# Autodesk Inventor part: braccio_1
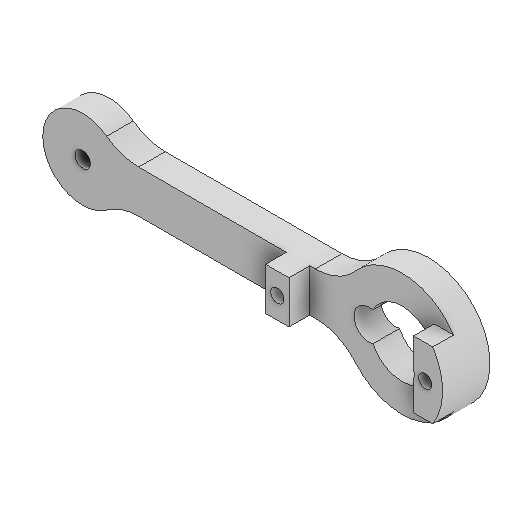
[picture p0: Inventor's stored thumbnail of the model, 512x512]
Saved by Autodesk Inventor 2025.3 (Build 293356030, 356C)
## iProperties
Created: 2026-03
Part Number: braccio_1
Material: Generico
Document SubType Name: Modeling
Designer: Ryzen5700u
Density: 1 g/cm^3
Appearance: Default
Author: Ryzen5700u
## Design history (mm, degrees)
sketch "Schizzo1"
  geometry: L1 (-60, 4)-(0, 4); L2 (0, 4)-(0, -4); L3 (0, -4)-(-60, -4); L4 (-60, -4)-(-60, 4); L5 (0, 0)-(13.023, 0); C1 r 11.5 at (0, 0); C2 r 7.5 at (-60, 0); 5 further points
  constraints: 10 end point, 2 centre point, 2 horizontal, 2 midpoint, 2 parallel, 1 coincident, 1 perpendicular, 1 other
  dimensions: "d0" = 23 diameter of C1; "d3" = 60 distance of L1.start L1.end; "d4" = 15 diameter of C2; "d16" = 8 distance between parallel lines of L1 L3
extrude "Estrusione1" new body sketch "Schizzo1" distance "d1" = 5; taper "d2" = 0 deg
fillet "Raccordo1" dims "d5" = 10
sketch "Schizzo2"
  geometry: L1 (-0.548, -2.337)-(-0.45, -2.358) reference; L2 (-0.569, -2.434)-(-0.548, -2.337) reference; L3 (-0.694, -2.298)-(-0.725, -2.393) reference; L4 (-0.789, -2.267)-(-0.694, -2.298) reference; L5 (-0.82, -2.362)-(-0.789, -2.267) reference; L6 (-0.93, -2.213)-(-0.971, -2.304) reference; L7 (-1.022, -2.172)-(-0.93, -2.213) reference; L8 (-1.062, -2.263)-(-1.022, -2.172) reference; L9 (-1.157, -2.103)-(-1.206, -2.19) reference; L10 (-1.243, -2.053)-(-1.157, -2.103) reference; L11 (-1.293, -2.14)-(-1.243, -2.053) reference; L12 (-1.37, -1.971)-(-1.429, -2.052) reference; L13 (-1.451, -1.912)-(-1.37, -1.971) reference; L14 (-1.51, -1.993)-(-1.451, -1.912) reference; L15 (-1.569, -1.817)-(-1.635, -1.891) reference; L16 (-1.643, -1.75)-(-1.569, -1.817) reference; L17 (-1.71, -1.824)-(-1.643, -1.75) reference; L18 (-1.75, -1.643)-(-1.824, -1.71) reference; L19 (-1.817, -1.569)-(-1.75, -1.643) reference; L20 (-1.891, -1.635)-(-1.817, -1.569) reference; L21 (-1.912, -1.451)-(-1.993, -1.51) reference; L22 (-1.971, -1.37)-(-1.912, -1.451) reference; L23 (-2.052, -1.429)-(-1.971, -1.37) reference; L24 (-2.053, -1.243)-(-2.14, -1.293) reference; L25 (-2.103, -1.157)-(-2.053, -1.243) reference; L26 (-2.19, -1.206)-(-2.103, -1.157) reference; L27 (-2.172, -1.022)-(-2.263, -1.062) reference; L28 (-2.213, -0.93)-(-2.172, -1.022) reference; L29 (-2.304, -0.971)-(-2.213, -0.93) reference; L30 (-2.267, -0.789)-(-2.362, -0.82) reference; L31 (-2.298, -0.694)-(-2.267, -0.789) reference; L32 (-2.393, -0.725)-(-2.298, -0.694) reference; L33 (-2.337, -0.548)-(-2.434, -0.569) reference; L34 (-2.358, -0.45)-(-2.337, -0.548) reference; L35 (-2.455, -0.471)-(-2.358, -0.45) reference; L36 (-2.382, -0.301)-(-2.481, -0.311) reference; L37 (-2.392, -0.201)-(-2.382, -0.301) reference; L38 (-2.491, -0.212)-(-2.392, -0.201) reference; L39 (-2.4, -0.05)-(-2.499, -0.05) reference; L40 (-2.4, 0.05)-(-2.4, -0.05) reference; L41 (-2.499, 0.05)-(-2.4, 0.05) reference; L42 (-2.392, 0.201)-(-2.491, 0.212) reference; L43 (-2.382, 0.301)-(-2.392, 0.201) reference; L44 (-2.481, 0.311)-(-2.382, 0.301) reference; L45 (-2.358, 0.45)-(-2.455, 0.471) reference; L46 (-2.337, 0.548)-(-2.358, 0.45) reference; L47 (-2.434, 0.569)-(-2.337, 0.548) reference; L48 (-2.298, 0.694)-(-2.393, 0.725) reference; L49 (-2.267, 0.789)-(-2.298, 0.694) reference; L50 (-2.362, 0.82)-(-2.267, 0.789) reference; L51 (-2.213, 0.93)-(-2.304, 0.971) reference; L52 (-2.172, 1.022)-(-2.213, 0.93) reference; L53 (-2.263, 1.062)-(-2.172, 1.022) reference; L54 (-2.103, 1.157)-(-2.19, 1.206) reference; L55 (-2.053, 1.243)-(-2.103, 1.157) reference; L56 (-2.14, 1.293)-(-2.053, 1.243) reference; L57 (-1.971, 1.37)-(-2.052, 1.429) reference; L58 (-1.912, 1.451)-(-1.971, 1.37) reference; L59 (-1.993, 1.51)-(-1.912, 1.451) reference; L60 (-1.817, 1.569)-(-1.891, 1.635) reference; L61 (-1.75, 1.643)-(-1.817, 1.569) reference; L62 (-1.824, 1.71)-(-1.75, 1.643) reference; L63 (-1.643, 1.75)-(-1.71, 1.824) reference; L64 (-1.569, 1.817)-(-1.643, 1.75) reference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; A1 r 6 centre (0, 0) between (-5.416, -2.584) and (-5.416, 2.584) reference; A2 r 2.7 centre (-6.2, 0) between (-5.416, 2.584) and (-5.416, -2.584) reference; A3 r 2.5 centre (0, 0) between (-0.725, -2.393) and (-0.569, -2.434) reference; A4 r 2.5 centre (0, 0) between (-0.971, -2.304) and (-0.82, -2.362) reference; A5 r 2.5 centre (0, 0) between (-1.206, -2.19) and (-1.062, -2.263) reference; A6 r 2.5 centre (0, 0) between (-1.429, -2.052) and (-1.293, -2.14) reference; A7 r 2.5 centre (0, 0) between (-1.635, -1.891) and (-1.51, -1.993) reference; A8 r 2.5 centre (0, 0) between (-1.824, -1.71) and (-1.71, -1.824) reference; A9 r 2.5 centre (0, 0) between (-1.993, -1.51) and (-1.891, -1.635) reference; A10 r 2.5 centre (0, 0) between (-2.14, -1.293) and (-2.052, -1.429) reference; A11 r 2.5 centre (0, 0) between (-2.263, -1.062) and (-2.19, -1.206) reference; A12 r 2.5 centre (0, 0) between (-2.362, -0.82) and (-2.304, -0.971) reference; A13 r 2.5 centre (0, 0) between (-2.434, -0.569) and (-2.393, -0.725) reference; A14 r 2.5 centre (0, 0) between (-2.481, -0.311) and (-2.455, -0.471) reference; A15 r 2.5 centre (0, 0) between (-2.499, -0.05) and (-2.491, -0.212) reference; A16 r 2.5 centre (0, 0) between (-2.491, 0.212) and (-2.499, 0.05) reference; A17 r 2.5 centre (0, 0) between (-2.455, 0.471) and (-2.481, 0.311) reference; A18 r 2.5 centre (0, 0) between (-2.393, 0.725) and (-2.434, 0.569) reference; A19 r 2.5 centre (0, 0) between (-2.304, 0.971) and (-2.362, 0.82) reference; A20 r 2.5 centre (0, 0) between (-2.19, 1.206) and (-2.263, 1.062) reference; A21 r 2.5 centre (0, 0) between (-2.052, 1.429) and (-2.14, 1.293) reference; A22 r 2.5 centre (0, 0) between (-1.891, 1.635) and (-1.993, 1.51) reference; A23 r 2.5 centre (0, 0) between (-1.71, 1.824) and (-1.824, 1.71) reference; A24 r 2.5 centre (0, 0) between (-1.51, 1.993) and (-1.635, 1.891) reference; A25 r 2.5 centre (0, 0) between (-1.293, 2.14) and (-1.429, 2.052) reference; A26 r 2.5 centre (0, 0) between (-1.062, 2.263) and (-1.206, 2.19) reference; A27 r 2.5 centre (0, 0) between (-0.82, 2.362) and (-0.971, 2.304) reference; A28 r 2.5 centre (0, 0) between (-0.569, 2.434) and (-0.725, 2.393) reference; A29 r 2.5 centre (0, 0) between (-0.311, 2.481) and (-0.471, 2.455) reference; A30 r 2.5 centre (0, 0) between (-0.05, 2.499) and (-0.212, 2.491) reference; A31 r 2.5 centre (0, 0) between (0.212, 2.491) and (0.05, 2.499) reference; A32 r 2.5 centre (0, 0) between (0.471, 2.455) and (0.311, 2.481) reference; A33 r 2.5 centre (0, 0) between (0.725, 2.393) and (0.569, 2.434) reference; A34 r 2.5 centre (0, 0) between (0.971, 2.304) and (0.82, 2.362) reference; A35 r 2.5 centre (0, 0) between (1.206, 2.19) and (1.062, 2.263) reference; A36 r 2.5 centre (0, 0) between (1.429, 2.052) and (1.293, 2.14) reference; A37 r 2.5 centre (0, 0) between (1.635, 1.891) and (1.51, 1.993) reference; A38 r 2.5 centre (0, 0) between (1.824, 1.71) and (1.71, 1.824) reference; A39 r 2.5 centre (0, 0) between (1.993, 1.51) and (1.891, 1.635) reference; A40 r 2.5 centre (0, 0) between (2.14, 1.293) and (2.052, 1.429) reference; A41 r 2.5 centre (0, 0) between (2.263, 1.062) and (2.19, 1.206) reference; A42 r 2.5 centre (0, 0) between (2.362, 0.82) and (2.304, 0.971) reference; A43 r 2.5 centre (0, 0) between (2.434, 0.569) and (2.393, 0.725) reference; A44 r 2.5 centre (0, 0) between (2.481, 0.311) and (2.455, 0.471) reference; A45 r 2.5 centre (0, 0) between (2.499, 0.05) and (2.491, 0.212) reference; A46 r 2.5 centre (0, 0) between (2.491, -0.212) and (2.499, -0.05) reference; A47 r 2.5 centre (0, 0) between (2.455, -0.471) and (2.481, -0.311) reference; A48 r 2.5 centre (0, 0) between (2.393, -0.725) and (2.434, -0.569) reference; A49 r 2.5 centre (0, 0) between (2.304, -0.971) and (2.362, -0.82) reference; A50 r 2.5 centre (0, 0) between (2.19, -1.206) and (2.263, -1.062) reference; A51 r 2.5 centre (0, 0) between (2.052, -1.429) and (2.14, -1.293) reference; A52 r 2.5 centre (0, 0) between (1.891, -1.635) and (1.993, -1.51) reference; A53 r 2.5 centre (0, 0) between (1.71, -1.824) and (1.824, -1.71) reference; A54 r 2.5 centre (0, 0) between (1.51, -1.993) and (1.635, -1.891) reference; A55 r 2.5 centre (0, 0) between (1.293, -2.14) and (1.429, -2.052) reference; A56 r 2.5 centre (0, 0) between (1.062, -2.263) and (1.206, -2.19) reference; A57 r 2.5 centre (0, 0) between (0.82, -2.362) and (0.971, -2.304) reference; A58 r 2.5 centre (0, 0) between (0.569, -2.434) and (0.725, -2.393) reference; A59 r 2.5 centre (0, 0) between (0.311, -2.481) and (0.471, -2.455) reference; A60 r 2.5 centre (0, 0) between (0.05, -2.499) and (0.212, -2.491) reference; A61 r 2.5 centre (0, 0) between (-0.212, -2.491) and (-0.05, -2.499) reference; A62 r 2.5 centre (0, 0) between (-0.471, -2.455) and (-0.311, -2.481) reference; A63 r 6.15 centre (0, 0) between (-5.495, -2.762) and (-5.495, 2.762); A64 r 2.85 centre (-6.2, 0) between (-5.495, 2.762) and (-5.495, -2.762); 1 further point
  constraints: 4 point on circle, 2 centre point, 1 other
  dimensions: "d6" = 0.15 radial gap between concentric circles of A1 A63
extrude "Estrusione2" cut sketch "Schizzo2" extent not by distance; stored distance "d7" = 0; taper "d8" = 0 deg
sketch "Schizzo3"
  geometry: A1 r 7.5 centre (60, 0) between (55.5, -6) and (55.5, 6) reference; 2 further points
  constraints: 1 coincident
hole "Foro1" sketch "Schizzo3" at (60, 0) diameter "d9" = 2.9; stored, may be unused: countersink angle "d13" = 82 deg, drill point angle "d15" = 118 deg; dims "d10" = 6, "d11" = 4.5, "d12" = 2, "d14" = 8
sketch "Schizzo4"
  geometry: A1 r 1 centre (19.55, 0) between (20.35, 0.6) and (20.35, -0.6) reference; A2 r 1 centre (-8.25, 0) between (-9.05, -0.6) and (-9.05, 0.6) reference; 1 further point
hole "Foro2" sketch "Schizzo4" at (-8.25, 0), (19.55, 0) diameter "d17" = 2.5; stored, may be unused: countersink angle "d21" = 90 deg, drill point angle "d23" = 118 deg; dims "d18" = 6, "d19" = 4.5, "d20" = 1, "d22" = 8
sketch "Schizzo5" dims "d0" = 23, "d3" = 60, "d4" = 15, "d16" = 8
  geometry: L1 (-5.85, 6.25)-(-5.85, -6.25) reference; L2 (-5.85, 6.25)-(-10.45, 6.25) reference; L3 (-10.45, 6.25)-(-10.45, 0.6) reference; L4 (-10.45, 0.6)-(-9.05, 0.6) reference; L5 (-9.05, -0.6)-(-10.45, -0.6) reference; L6 (-10.45, -0.6)-(-10.45, -6.25) reference; L7 (-5.85, -6.25)-(-10.45, -6.25) reference; L8 (17.15, -6.25)-(17.15, 6.25) reference; L9 (17.15, -6.25)-(21.75, -6.25) reference; L10 (21.75, -6.25)-(21.75, -0.6) reference; L11 (21.75, -0.6)-(20.35, -0.6) reference; L12 (20.35, 0.6)-(21.75, 0.6) reference; L13 (21.75, 0.6)-(21.75, 6.25) reference; L14 (17.15, 6.25)-(21.75, 6.25) reference; L15 (49.5, -4)-(16.317, -4) reference; L16 (16.317, 4)-(49.5, 4) reference; L17 (-5.85, 6.25)-(-10.45, 6.25); L18 (-10.45, 6.25)-(-10.45, -6.25); L19 (-10.45, -6.25)-(-5.85, -6.25); L20 (-5.85, -6.25)-(-5.85, 6.25); L21 (17.15, 6.25)-(21.75, 6.25); L22 (21.75, 6.25)-(21.75, -6.25); L23 (21.75, -6.25)-(17.15, -6.25); L24 (17.15, -6.25)-(17.15, 6.25); C1 r 2.25 at (19.55, 0) reference; C2 r 2.25 at (60, 0) reference; C3 r 1.25 at (-8.25, 0) reference; C4 r 1.25 at (19.55, 0) reference; A1 r 1 centre (-8.25, 0) between (-9.05, -0.6) and (-9.05, 0.6) reference; A2 r 1 centre (19.55, 0) between (20.35, 0.6) and (20.35, -0.6) reference; A3 r 2.25 centre (-8.25, 0) between (-6.111, 0.697) and (-6.111, -0.697) reference; A4 r 6.15 centre (0, 0) between (-6.111, -0.697) and (5.495, -2.762) reference; A5 r 2.85 centre (6.2, 0) between (5.495, -2.762) and (5.495, 2.762) reference; A6 r 10 centre (16.317, -14) between (16.317, -4) and (8.728, -7.488) reference; A7 r 10 centre (49.5, -14) between (55.5, -6) and (49.5, -4) reference; A8 r 7.5 centre (60, 0) between (55.5, -6) and (55.5, 6) reference; A9 r 10 centre (49.5, 14) between (49.5, 4) and (55.5, 6) reference; A10 r 10 centre (16.317, 14) between (8.728, 7.488) and (16.317, 4) reference; A11 r 11.5 centre (0, 0) between (8.728, 7.488) and (8.728, -7.488) reference; A12 r 6.15 centre (0, 0) between (5.495, 2.762) and (-6.111, 0.697) reference; 16 further points
  constraints: 16 end point, 4 parallel, 2 horizontal, 2 perpendicular
extrude "Estrusione3" join sketch "Schizzo5" distance "d24" = 3.9; taper "d25" = 0 deg
sketch "Schizzo6"
  geometry: L1 (-16.317, 4)-(-49.5, 4) reference; L2 (-49.5, -4)-(-16.317, -4) reference; L3 (-17.15, 6.25)-(-21.75, 6.25) reference; L4 (-21.75, 0.6)-(-21.75, 6.25) reference; L5 (-17.15, -6.25)-(-17.15, 6.25) reference; L6 (-17.15, -6.25)-(-21.75, -6.25) reference; L7 (5.85, 6.25)-(10.45, 6.25) reference; L8 (10.45, 6.25)-(10.45, 0.6) reference; L9 (5.85, 6.25)-(5.85, -6.25) reference; L10 (5.85, -6.25)-(10.45, -6.25) reference; L11 (10.45, 6.25)-(5.85, 6.25); L12 (5.85, 6.25)-(5.85, -6.25); L13 (5.85, -6.25)-(10.45, -6.25); L14 (10.45, -6.25)-(10.45, 6.25); L15 (-21.75, 6.25)-(-17.15, 6.25); L16 (-17.15, 6.25)-(-17.15, -6.25); L17 (-17.15, -6.25)-(-21.75, -6.25); L18 (-21.75, -6.25)-(-21.75, 6.25); L19 (-17.35, 6.25)-(-17.35, -6.25); L20 (6.05, 6.25)-(6.05, -6.25); C1 r 1.25 at (-19.55, 0) reference; C2 r 1.25 at (8.25, 0) reference; C3 r 1.45 at (-60, 0) reference; A1 r 6.15 centre (0, 0) between (-5.495, -2.762) and (-5.495, 2.762) reference; A2 r 2.85 centre (-6.2, 0) between (-5.495, 2.762) and (-5.495, -2.762) reference; A3 r 11.5 centre (0, 0) between (-8.728, -7.488) and (-8.728, 7.488) reference; A4 r 10 centre (-16.317, 14) between (-16.317, 4) and (-8.728, 7.488) reference; A5 r 10 centre (-49.5, 14) between (-55.5, 6) and (-49.5, 4) reference; A6 r 7.5 centre (-60, 0) between (-55.5, 6) and (-55.5, -6) reference; A7 r 10 centre (-49.5, -14) between (-49.5, -4) and (-55.5, -6) reference; A8 r 10 centre (-16.317, -14) between (-8.728, -7.488) and (-16.317, -4) reference; 18 further points
  constraints: 20 end point, 4 parallel, 4 perpendicular, 4 point on line, 2 horizontal
  dimensions: "d28" = 0.2 distance between parallel lines of L5 L19; "d29" = 0.2 distance between parallel lines of L9 L20
extrude "Estrusione4" join sketch "Schizzo6" distance "d26" = 3.9; taper "d27" = 0 deg
node "Solido1"
node "Riferimento1"
node "Riferimento2"
node "Riferimento3"
node "Riferimento4"
node "Riferimento5"
node "Linea chiusa proiettata1"
node "Linea chiusa proiettata2"
